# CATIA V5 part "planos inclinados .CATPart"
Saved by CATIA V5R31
Part number: planos inclinados 
Bounding box of the stored display mesh (mm): x -40.705 to 40.705, y 0 to 156.6, z 0 to 3.3
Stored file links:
  C:\Users\189361\Desktop\planos inclinados .CATPart
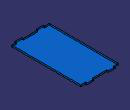
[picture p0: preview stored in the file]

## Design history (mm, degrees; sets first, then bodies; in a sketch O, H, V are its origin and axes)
Body1 (main body)
  Sketch1 on xy-plane, origin (0, 0, 0), H (1, 0, 0), V (0, 1, 0)
    point P1 (0, 3.3)
    line L1 (0, 3.3) -> (-15.705, 3.3)
    point P2 (-15.705, 3.3)
    line L2 (-15.705, 3.3) -> (-15.705, 0)
    point P3 (-15.705, 0)
    line L3 (-15.705, 0) -> (-30.705, 0)
    point P4 (-30.705, 0)
    line L4 (-30.705, 0) -> (-30.705, 3.3)
    point P5 (-30.705, 3.3)
    line L5 (-30.705, 3.3) -> (-40.705, 3.3)
    point P6 (-40.705, 3.3)
    line L6 (-40.705, 3.3) -> (-40.705, 153.3)
    point P7 (-40.705, 153.3)
    line L7 (-40.705, 153.3) -> (-30.705, 153.3)
    point P8 (-30.705, 153.3)
    line L8 (-30.705, 153.3) -> (-30.705, 156.6)
    point P9 (-30.705, 156.6)
    line L9 (-30.705, 156.6) -> (-15.705, 156.6)
    point P10 (-15.705, 156.6)
    line L10 (-15.705, 156.6) -> (-15.705, 153.3)
    point P11 (-15.705, 153.3)
    line L11 (-15.705, 153.3) -> (0, 153.3)
    point P12 (0, 153.3)
    point P13 (0, 3.3)
    point P14 (15.705, 3.3)
    point P15 (30.705, 3.3)
    point P16 (40.705, 3.3)
    point P17 (40.705, 153.3)
    point P18 (30.705, 153.3)
    point P19 (30.705, 156.6)
    point P20 (15.705, 156.6)
    point P21 (15.705, 153.3)
    point P22 (0, 153.3)
    line L12 (0, 3.3) -> (15.705, 3.3)
    line L13 (30.705, 3.3) -> (40.705, 3.3)
    line L14 (40.705, 3.3) -> (40.705, 153.3)
    line L15 (40.705, 153.3) -> (30.705, 153.3)
    line L16 (30.705, 153.3) -> (30.705, 156.6)
    line L17 (30.705, 156.6) -> (15.705, 156.6)
    line L18 (15.705, 156.6) -> (15.705, 153.3)
    line L19 (15.705, 153.3) -> (0, 153.3)
    point P23 (30.705, 0)
    point P24 (15.705, 0)
    line L20 (15.705, 0) -> (30.705, 0)
    line L21 (15.705, 3.3) -> (15.705, 0)
    line L22 (30.705, 0) -> (30.705, 3.3)
    length L8 = 3.3
    length L9 = 15
    distance V L6 = 40.705
    distance L4 L6 = 10
    length L6 = 150
    coincidence: P1 V, P3 H, P5 L1, P8 L4, P10 L2, P11 L7, P12 V, P1 P13, P12 P22
    horizontal: L1 H, L3 H, L5 H, L7 H, L9 H, L11 H
    vertical: L2 V, L4 V, L6 V, L8 V, L10 V
    equal size: L2 L4, L4 L8, L8 L10
    symmetry: P1 P13 V, P2 P14 V, P5 P15 V, P6 P16 V, P7 P17 V, P8 P18 V, P9 P19 V, P10 P20 V, P11 P21 V, P12 P22 V, L1 L12 V, L5 L13 V, L6 L14 V, L7 L15 V, L8 L16 V, L9 L17 V, L10 L18 V, L11 L19 V, P4 P23 V, P3 P24 V, L3 L20 V, L2 L21 V, L4 L22 V
  Pad1: profile Sketch1, direction (0, 0, 1), length 3.3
